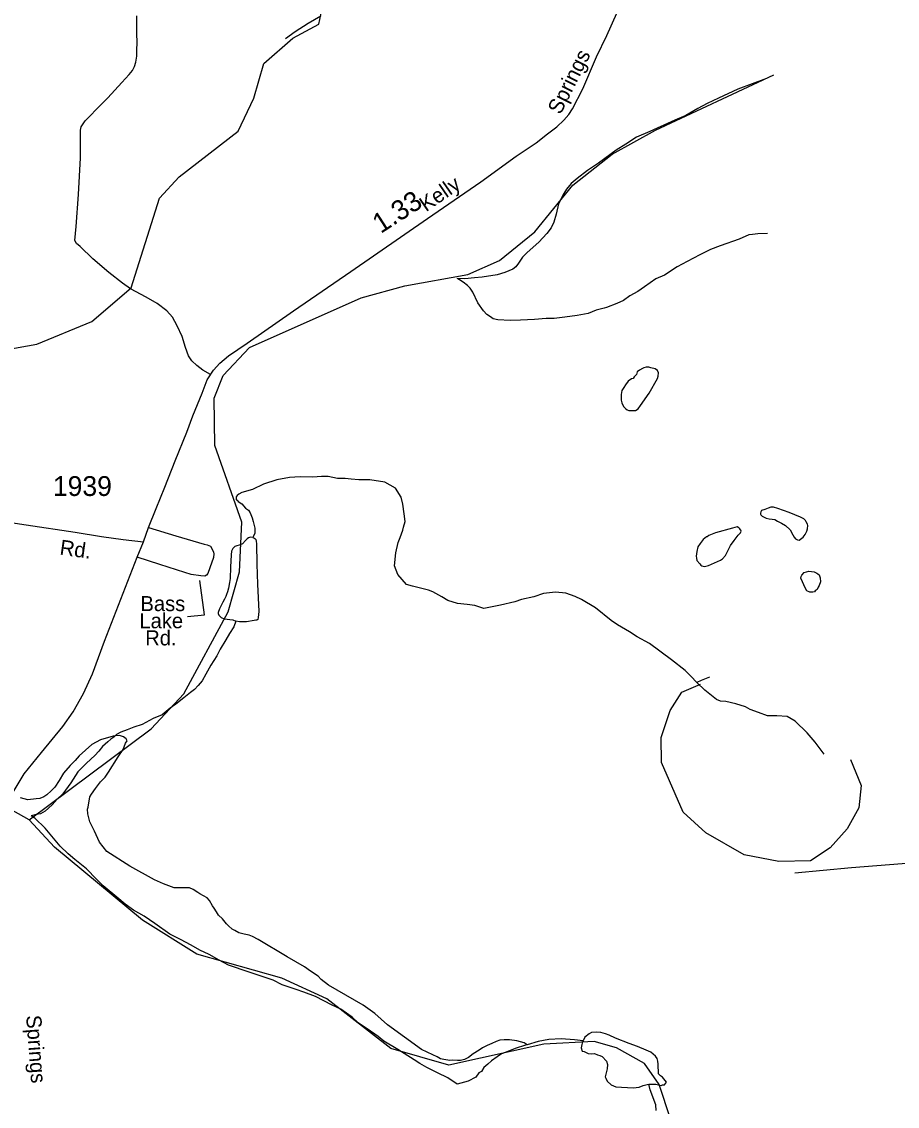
# Model space of a CAD drawing. Extents: x 2206922 to 2357709, y 510027 to 673830.
# Drawn here: x 2288307 to 2293828, y 540656 to 547499 of the extents above; entities that cross this region are included whole.
import ezdxf

# ---------------------------------------------------------------- set-up
doc = ezdxf.new("R2010")
doc.units = 0
for name, color, linetype in [('Exist Hydrographic Creek Single Shore', 7, 'Continuous'), ('Exist Hydrographic Misc Water Feature', 7, 'Continuous'), ('Exist Hydrographic Pond Under 1500 Sq Ft', 7, 'Continuous'), ('Exist Road Non-System Type 51', 7, 'Continuous'), ('Exist Road Non-System Type 51 Label', 7, 'Continuous'), ('Exist Road Secondary Mileage Hundredths English Label', 7, 'Continuous'), ('Exist Road Secondary Type 51 Attributed', 7, 'Continuous'), ('Exist Road Secondary Type 51 Label', 7, 'Continuous'), ('Exist Road Secondary Type 51 Number Label', 7, 'Continuous')]:
    doc.layers.add(name, color=color, linetype=linetype)

msp = doc.modelspace()

# ---------------------------------------------------------------- linework, layer by layer
at = {"layer": 'Exist Hydrographic Creek Single Shore'}
for points in [[(2288355, 542464.3), (2288012, 542654.8), (2287845, 542668), (2287204, 542628.5), (2286663.9, 542531.1), (2286354.9, 542537.3), (2286064, 542585.8), (2285821, 542708.8), (2285661, 542872.7), (2285557.9, 543153.6), (2285515.9, 544171.1), (2285319.8, 544601.4), (2285059, 544898.5), (2285059, 544931.3)], [(2295399.2, 540941.6), (2294538.1, 540365.3), (2293899, 540102.7), (2293469, 539773.6), (2293344.1, 539730.3), (2293186, 539720.3), (2292960.1, 539842.9), (2292683, 540107.5), (2292472, 540354.5), (2292327.1, 540793.6), (2292234, 540926.6), (2292058, 541025.3), (2291915.9, 541064.3), (2291600, 541047.7), (2291001, 540915.4), (2290634, 541021.2), (2290231, 541334.3), (2289947, 541464.7), (2289412, 541616.5), (2289069, 541830), (2288514.9, 542290.5), (2288355, 542464.3)]]:
    msp.add_lwpolyline(points, dxfattribs=at)
at = {"layer": 'Exist Hydrographic Misc Water Feature'}
for points in [[(2290015.9, 547395.9), (2290180, 547484.4), (2290267.9, 547899.1), (2290432, 548125.4), (2291134.9, 548626.1), (2291316, 548835.6), (2291685, 549497.1), (2291824.9, 549615.7), (2292390, 549784.7), (2292653.9, 550022), (2292743.9, 550207.1), (2292758.9, 550462.6), (2292714, 550765.2), (2292587.1, 551030.2), (2292292, 551400.1), (2291764, 551702.6), (2291133.9, 552299.1), (2290898.9, 552477.7), (2290807, 552486.1), (2290557.9, 552425.5), (2290143.9, 552165)], [(2290193.1, 547534.2), (2290113.9, 547487.3), (2290031.1, 547436.2), (2289970.2, 547391.8)], [(2285059, 544931.3), (2285433, 544986), (2286182.9, 544984), (2286556.9, 545045.4), (2286748, 545097.3), (2286954.9, 545240.7), (2287079, 545284.1), (2287462, 545322.3), (2287778, 545417.6), (2288202, 545428.6), (2288402, 545464), (2288749.9, 545607.9), (2288998, 545819.3), (2289176, 546386.4), (2289299.9, 546521.6), (2289672.1, 546809.3), (2289769.9, 547017.1), (2289834, 547235.6), (2290015.9, 547395.9)], [(2288355, 542464.3), (2289123.9, 543039), (2289330, 543257.9), (2289608.9, 543777), (2289681.1, 544028), (2289695, 544342.6), (2289524, 544824.8), (2289520.9, 545123.3), (2289577.9, 545266.5), (2289743, 545443.5), (2290448, 545757.3), (2290721.9, 545833.7), (2291121, 545904.4), (2291320.1, 545992.2), (2291542.9, 546174.6), (2291782, 546468.3), (2292029.9, 546663.3), (2292303.9, 546815.2), (2293050.1, 547164.2)], [(2293002.5, 547140.3), (2292821.7, 547074.7), (2292699.9, 547017.6), (2292628.7, 546982.9), (2292570.5, 546952.3), (2292495, 546907.7), (2292425.7, 546878.8), (2292268.4, 546807.6), (2292182.7, 546770.7), (2292115.5, 546726.1), (2292055.4, 546689.7), (2291944.2, 546606.7), (2291874.9, 546559.9), (2291809.5, 546509.4), (2291771.6, 546479), (2291741.8, 546442.9), (2291726.1, 546414.8), (2291691.2, 546350.4), (2291677.7, 546284.3), (2291662.1, 546234.3), (2291644.7, 546198.1), (2291618.8, 546163.8), (2291566.9, 546107.5), (2291493.7, 546042.7), (2291464.4, 546014.3), (2291438.6, 545976.4), (2291422.6, 545952.1), (2291402.9, 545938), (2291353.5, 545917.5), (2291305.3, 545903.2), (2291211.4, 545888.2), (2291161.8, 545883.9), (2291101.5, 545877.1), (2291053.7, 545878.7)], [(2293008.3, 546163), (2292947.8, 546160.3), (2292913.9, 546156.1), (2292892, 546153.7), (2292830.1, 546127.4), (2292710.7, 546086.1), (2292649.2, 546061.3), (2292583.4, 546029.1), (2292502, 545986.2), (2292440.5, 545953.7), (2292360.7, 545900.8), (2292305.1, 545876.3), (2292233.4, 545825.9), (2292191.7, 545797.3), (2292142.3, 545769.1), (2292100.5, 545740.5), (2292058.4, 545722.1), (2291994.9, 545695.6), (2291978.9, 545691.5), (2291929.3, 545679.1), (2291879, 545658.7), (2291809.5, 545646.1), (2291731.6, 545635.1), (2291663.7, 545626.6), (2291613.5, 545626.1), (2291539.7, 545621.4), (2291451.7, 545616.8), (2291386.3, 545614.1), (2291308.2, 545619.3), (2291280.1, 545624.8), (2291262.2, 545636.8), (2291239.7, 545652.8), (2291219.6, 545674.5), (2291183.1, 545726.2), (2291150.5, 545793.5), (2291134.1, 545817.5), (2291117.9, 545835.4), (2291090, 545857), (2291067.8, 545870.9), (2291053.7, 545878.7)], [(2292131.4, 545231), (2292113.2, 545209), (2292103.6, 545191), (2292091.5, 545172.9), (2292085.9, 545146.6), (2292086.3, 545110.9), (2292090.4, 545094.8), (2292100.5, 545071), (2292113, 545059), (2292124.9, 545051.1), (2292134.7, 545047.2), (2292151.1, 545045.6), (2292158.7, 545045.6), (2292177, 545045.7), (2292194.8, 545056), (2292208.8, 545077.8), (2292263.9, 545156.3), (2292315, 545248.8), (2292320.7, 545262.9), (2292322.8, 545284.9), (2292316.4, 545298.8), (2292300.2, 545308.5), (2292274, 545316.6), (2292260.2, 545320.3), (2292244.4, 545320.2), (2292230.1, 545315.9), (2292222.1, 545311.8), (2292202.2, 545301.8), (2292188.2, 545289.7), (2292182.7, 545273.5), (2292174.5, 545265.4), (2292168.8, 545259.4), (2292162.8, 545249.3), (2292152.8, 545247.2), (2292131.4, 545231)], [(2292564.7, 543330.4), (2292526.4, 543369.9), (2292490.1, 543405.7), (2292403.6, 543472.7), (2292264.7, 543575.5), (2292188, 543618.7), (2292140.3, 543650.2), (2292063.8, 543693.3), (2292023.2, 543720.9), (2291925, 543801.9), (2291836.2, 543853.3), (2291796, 543872.8), (2291738, 543894.1), (2291671.7, 543899.6), (2291598.1, 543890.8), (2291536.4, 543870.5), (2291458.5, 543853.8), (2291416.4, 543839.1), (2291325, 543818.4), (2291221.2, 543797.6), (2291164.8, 543816.9), (2291114.8, 543822.5), (2291054.9, 543827.9), (2290994.4, 543847.5), (2290956.7, 543871), (2290900.3, 543902.2), (2290872.2, 543912.1), (2290838, 543921.7), (2290771.7, 543937.4), (2290734.2, 543948.7), (2290679.3, 544012.1), (2290656.9, 544066.2), (2290666.1, 544147.9), (2290681.5, 544214.2), (2290693.2, 544246.1), (2290710.6, 544290.5), (2290714.5, 544310.6), (2290724.4, 544346.4), (2290719.5, 544394.6), (2290711.1, 544456.2), (2290700.6, 544500.4), (2290664.3, 544555.7), (2290596.2, 544593.2), (2290501.9, 544608.2), (2290432, 544609.8), (2290384, 544613), (2290345.9, 544616.7), (2290298.1, 544618.2), (2290240.3, 544629.8), (2290198, 544629.3), (2290142, 544625.1), (2290063.9, 544627.9), (2289996, 544623.6), (2289916.3, 544608.9), (2289832.2, 544582.1), (2289762.7, 544547.6), (2289695, 544529), (2289677.2, 544518.7)], [(2289677.2, 544518.7), (2289665.1, 544510.4), (2289659.5, 544502.3), (2289659.7, 544482.4), (2289665.7, 544480.7), (2289671.6, 544472.5), (2289695.8, 544456.7), (2289717.8, 544431.1), (2289738.1, 544417.5), (2289748.1, 544401.4), (2289760.6, 544369.5), (2289767, 544345.4), (2289777.4, 544303.7), (2289777.7, 544271.6), (2289769.5, 544253.8), (2289763.9, 544245.7)], [(2293238.9, 544361.9), (2293218.4, 544373.9), (2293146.3, 544403), (2293074.5, 544428.4), (2293048, 544436), (2293029.8, 544435.9), (2293014.2, 544429.7), (2292992.1, 544421.7), (2292972, 544415.4), (2292966.4, 544407.4), (2292966.2, 544399.3), (2292966.2, 544391.5), (2292966.4, 544387.5), (2292974.8, 544379.7), (2293000.5, 544367.8), (2293020.8, 544363.9), (2293038.8, 544360.4), (2293054.6, 544358.4), (2293073, 544348.7), (2293097, 544336.6), (2293123.3, 544320.9), (2293153, 544293.3), (2293169.8, 544261.5), (2293177.8, 544247.4), (2293185.8, 544237.7), (2293189.9, 544233.8), (2293197.7, 544229.8), (2293208, 544227.8), (2293218, 544234), (2293234, 544247.9), (2293247.8, 544264.1), (2293257.4, 544286.1), (2293261.3, 544300.1), (2293262.9, 544320.5), (2293261.3, 544330.1), (2293252.5, 544344.4), (2293248.8, 544352.3), (2293238.9, 544361.9)], [(2292604.5, 544232.4), (2292584.2, 544208.2), (2292570.7, 544185.9), (2292563.3, 544155.8), (2292559.4, 544127.6), (2292561.2, 544114), (2292563.7, 544099.8), (2292581.7, 544078), (2292589.7, 544069.9), (2292595.9, 544066.2), (2292611.7, 544062.1), (2292627.9, 544066.6), (2292637.9, 544068.7), (2292713.4, 544101.2), (2292725.5, 544109.5), (2292745, 544131.7), (2292776.5, 544193.9), (2292798.5, 544225.9), (2292823.7, 544260.2), (2292829.9, 544266.2), (2292839.7, 544274.4), (2292843.4, 544284.4), (2292841.5, 544290.4), (2292839.5, 544294.2), (2292835.6, 544300.6), (2292829.6, 544306.3), (2292817.6, 544312.2), (2292789.3, 544303.9), (2292681.6, 544275.1), (2292639.8, 544258.7), (2292628.3, 544250.3), (2292624, 544248.5), (2292604.5, 544232.4)], [(2289763.9, 544245.7), (2289749.8, 544247.4), (2289737.7, 544243.2), (2289728, 544237.3), (2289718, 544227.1), (2289700.1, 544205.1), (2289694.4, 544203.1), (2289678, 544197), (2289664.1, 544192.6), (2289650.7, 544188.5), (2289638.4, 544176.6), (2289630.8, 544158.3), (2289628.8, 544136.3), (2289623.5, 544058.4), (2289622.2, 543986.5), (2289616.5, 543960.5), (2289610.9, 543924.5), (2289605.2, 543902.2), (2289599.1, 543886.1), (2289593.3, 543872.4), (2289585.5, 543856.1), (2289575.9, 543838.1), (2289566, 543820.1), (2289553.9, 543796), (2289545.9, 543771.7), (2289546.8, 543765.9), (2289550.7, 543755.9), (2289552.5, 543752), (2289565, 543740), (2289584.5, 543732.2), (2289638.6, 543724.9), (2289656.7, 543716.9)], [(2289763.9, 544245.7), (2289771.7, 544243.8), (2289777.9, 544239.6), (2289784.2, 544231.7), (2289785.9, 544221.7), (2289788.3, 544206), (2289789.3, 544076.1), (2289794.7, 543950), (2289802.1, 543778.1), (2289798.4, 543740.1), (2289796.3, 543728.3), (2289790.6, 543724.3), (2289783, 543724.2), (2289772.7, 543722.1), (2289724.8, 543713.5), (2289680.9, 543713.2), (2289656.7, 543716.9)], [(2293342.5, 543965.1), (2293334.5, 543943.1), (2293328.7, 543931.1), (2293323, 543917), (2293310.5, 543909.1), (2293305, 543903), (2293295.1, 543900.9), (2293276.9, 543900.8), (2293257, 543908.6), (2293248.6, 543922.4), (2293220.5, 543988), (2293222.1, 543998.2), (2293225.8, 544008.2), (2293239.5, 544024.3), (2293269.5, 544032.4), (2293303.7, 544028.9), (2293319.7, 544020.8), (2293327.7, 544015.1), (2293335.7, 544009.1), (2293342.1, 543991.1), (2293342.5, 543965.1)], [(2289656.7, 543716.9), (2289645.2, 543680.9), (2289617.3, 543640.5), (2289593.9, 543600.2), (2289558.5, 543540.3), (2289536.9, 543497.7), (2289499.2, 543439.7), (2289468.2, 543383.2), (2289444.7, 543341.3), (2289418.8, 543310.7), (2289396.9, 543286.8), (2289371.4, 543266.3), (2289329.4, 543234.1), (2289279.8, 543193.7), (2289244.3, 543167.4), (2289192.6, 543127), (2289136.7, 543102.6), (2289067.1, 543065.6), (2289013.4, 543049.4), (2288973.2, 543032.7), (2288932, 543016.6), (2288905.8, 543002.3), (2288895.9, 542994.1)], [(2292644.1, 543363.1), (2292590.6, 543342.7), (2292564.7, 543330.4)], [(2293366.3, 542878), (2293309.7, 542953.4), (2293259.2, 543012.9), (2293184.6, 543086.2), (2293132.7, 543115.9), (2293068.5, 543119.1), (2293008.5, 543120.4), (2292952.1, 543141.9), (2292900.2, 543159.4), (2292870, 543177.4), (2292809.8, 543196.6), (2292745.8, 543210.3), (2292713.8, 543211.8), (2292687.8, 543223.5), (2292615, 543282.7), (2292564.7, 543330.4)], [(2288895.9, 542994.1), (2288884, 542992.2), (2288804.3, 542969.4), (2288748.5, 542938.8), (2288669.1, 542868.1), (2288643.3, 542837.9), (2288612.1, 542805.7), (2288570.3, 542759.3), (2288542.8, 542711.1), (2288515.1, 542670.6), (2288493.4, 542646.8), (2288465.5, 542622.6), (2288446, 542608.1), (2288421.9, 542597.9), (2288398.3, 542595.8), (2288346, 542589.1), (2288322, 542597.2), (2288299.8, 542602.9)], [(2288895.9, 542994.1), (2288887.7, 542986), (2288870.1, 542972), (2288850.4, 542955.9), (2288816.8, 542927.3), (2288793, 542897.2), (2288769.2, 542869.2), (2288715.7, 542820.5), (2288662, 542766.1), (2288617.1, 542697.9), (2288567.4, 542627.5), (2288529.9, 542595), (2288498.3, 542558.8), (2288454.7, 542518.4), (2288425.1, 542502.1), (2288398.9, 542498), (2288366.9, 542489.4)], [(2291494.8, 541043.5), (2291474.5, 541057.5), (2291428.3, 541068.9), (2291382.4, 541076.6), (2291348.4, 541076.1), (2291322.5, 541073.9), (2291298.5, 541065.8), (2291270.6, 541053.3), (2291242.8, 541039.3), (2291213.2, 541025.1), (2291191.3, 541011), (2291153.8, 540986.6), (2291124, 540964.3), (2291099.8, 540952.1), (2291074.2, 540945.9), (2291054.1, 540945.6), (2291026, 540947.4), (2291006.1, 540945.2), (2290968, 540950.9), (2290948.1, 540956.4), (2290925.7, 540968.2), (2290899.7, 540980.2), (2290827.3, 541015.5), (2290614.1, 541171.3), (2290533.7, 541242.6), (2290460.9, 541293.7), (2290242.1, 541421.5), (2290195.8, 541457.3), (2290177.3, 541477.1), (2290127.3, 541508.6), (2290091.2, 541536.3), (2289980.5, 541599.2), (2289797.3, 541709.5), (2289763.3, 541727.2), (2289741.2, 541736.6), (2289709.4, 541742.6), (2289677.2, 541750.3), (2289650.7, 541766.1), (2289635.1, 541773.7), (2289610.7, 541795.6), (2289598.6, 541807.6), (2289572.4, 541839.1), (2289548.4, 541863), (2289535.9, 541882.7), (2289521.5, 541906.8), (2289509.4, 541920.7), (2289491.4, 541954.3), (2289477.3, 541972.2), (2289429.3, 541997.7), (2289417, 542005.7), (2289388.5, 542023.3), (2289364.5, 542035), (2289338.4, 542034.9), (2289313, 542034.7), (2289268.7, 542034.1), (2289200.2, 542059.4), (2289144.5, 542084.8), (2288989.8, 542171.3), (2288844.9, 542264.1), (2288798.3, 542323.5), (2288765.7, 542393.3), (2288751.6, 542420.9), (2288737, 542451.1), (2288729, 542484.8), (2288724.5, 542500.9), (2288722.3, 542530.8), (2288725.9, 542542.8), (2288737.4, 542608.8), (2288747.3, 542625.1), (2288773.3, 542661), (2288804.7, 542703.7), (2288832.6, 542733.5), (2288854.3, 542763.9), (2288915.4, 542860.6), (2288946.8, 542908.6), (2288962.4, 542946.7), (2288972.2, 542962.7), (2288966.3, 542974.9), (2288949.9, 542986.7), (2288923.8, 542996.4), (2288895.9, 542994.1)], [(2291494.8, 541043.5), (2291484.5, 541041.4), (2291419.1, 541020.8), (2291361.3, 540998.3), (2291331.5, 540988.2), (2291305.7, 540967.8), (2291269.8, 540943.6), (2291246, 540923.2), (2291220.2, 540901.1), (2291206.5, 540876.9), (2291190.3, 540866.8), (2291170.6, 540840.9), (2291121.2, 540814.3), (2291053.5, 540795.7), (2290993.2, 540836.8), (2290928.6, 540868.4), (2290862.4, 540901.9), (2290818.3, 540927.2), (2290781.8, 540948.9), (2290679.5, 541015.8), (2290591.1, 541067.2), (2290554.8, 541096.7), (2290484.5, 541146.2), (2290428.1, 541183.5), (2290389.9, 541219.2), (2290319, 541268.4), (2290265.5, 541293.9), (2290159.1, 541348.9), (2290086.7, 541376), (2290038.1, 541393.8), (2289949.9, 541423), (2289891.9, 541452.4), (2289741.8, 541503), (2289611.2, 541547.8), (2289552.9, 541579.3), (2289488.7, 541614.5), (2289430.3, 541641.9), (2289376.2, 541673.2), (2289307.7, 541708.6), (2289241.4, 541742.2), (2289147.1, 541809.1), (2289078.4, 541856.7), (2289012, 541893.9), (2288959.9, 541931.3), (2288907.2, 541977), (2288820.9, 542048), (2288778.4, 542089.6), (2288715.9, 542155), (2288641.5, 542214.1), (2288601.1, 542249.8), (2288548.8, 542297.4), (2288455.7, 542410.3), (2288389.5, 542473.8), (2288366.9, 542489.4)], [(2291846.2, 541068.8), (2291792.1, 541076.6), (2291708, 541081.5), (2291630.1, 541078.7), (2291564.3, 541066.3), (2291494.8, 541043.5)], [(2292260.8, 540795.1), (2292276.6, 540795.2), (2292288.5, 540795.4), (2292304.3, 540795.5), (2292338.8, 540787.9), (2292346.8, 540792), (2292360.7, 540791.9), (2292372.8, 540807.9), (2292364, 540819.7), (2292356.4, 540829.8), (2292346.5, 540839.8), (2292334, 540849.4), (2292330.1, 540853.6), (2292322.1, 540861.3), (2292319.3, 540921.3), (2292317.2, 540941.5), (2292312.9, 540957.2), (2292302.9, 540973.3), (2292274.8, 540999), (2292245, 541010.8), (2292190.5, 541034), (2292136.4, 541053.5), (2292050.2, 541086.8), (2292010.3, 541104.6), (2291987.5, 541114), (2291957.8, 541121.8), (2291931.7, 541123.7), (2291899.9, 541121.2), (2291885.8, 541113.2), (2291858.3, 541093), (2291846.2, 541068.8)], [(2291846.2, 541068.8), (2291842.5, 541062.9), (2291838.2, 541046.9), (2291834.5, 541024.7), (2291841.1, 541004.8), (2291853, 541002.9), (2291879.2, 540989.3), (2291901, 540987.6), (2291918.8, 540989.8), (2291937.1, 540981.7), (2291953.1, 540976.1), (2291967, 540969.9), (2291993.4, 540940.4), (2292001.2, 540920.6), (2291997.8, 540892.3), (2291986.1, 540842.2), (2291990.8, 540834.2), (2291998.4, 540814.4), (2292023, 540792.8), (2292052.9, 540779), (2292163.2, 540772.1), (2292180.9, 540774.3), (2292200.8, 540776.2), (2292224.7, 540786.8), (2292250.8, 540795), (2292260.8, 540795.1)], [(2292308.2, 540629.5), (2292305.7, 540665.5), (2292268.8, 540761.1), (2292260.8, 540795.1)]]:
    msp.add_lwpolyline(points, dxfattribs=at)
at = {"layer": 'Exist Hydrographic Pond Under 1500 Sq Ft'}
msp.add_lwpolyline([(2293532, 542845.2), (2293600, 542679.9), (2293585.1, 542539.2), (2293511, 542406.2), (2293404, 542287), (2293279.9, 542204.2), (2293080, 542201.7), (2292863.1, 542242.1), (2292620.1, 542381.5), (2292477, 542512.3), (2292341, 542826.6), (2292339, 542984.1), (2292396, 543153.4), (2292470, 543270), (2292586, 543320.1)], dxfattribs=at)
at = {"layer": 'Exist Road Non-System Type 51'}
for points in [[(2289498.5, 545273.2), (2289449.8, 545300.5), (2289410.6, 545330.2), (2289379.8, 545359.9), (2289359.6, 545390.8), (2289340.6, 545443), (2289318.1, 545513.1), (2289288.4, 545580.8), (2289258.7, 545635.4), (2289222, 545675.7), (2289161.4, 545720.9), (2289092.6, 545762.4), (2288994.1, 545814.7), (2288941.9, 545849.1), (2288857.6, 545918), (2288755.6, 546003.5), (2288674.9, 546080.7), (2288652.3, 546100.8), (2288642.8, 546119.8), (2288649.9, 546207.7), (2288665.4, 546408.4), (2288677.2, 546639.9), (2288677.2, 546783.6), (2288678.4, 546814.5), (2288682, 546835.8), (2288690.3, 546848.9), (2288708.1, 546873.8), (2288744.9, 546911.8), (2288773.4, 546940.3), (2288850.5, 547018.7), (2288939.5, 547114.9), (2288985.8, 547167.1), (2289004.8, 547190.9), (2289017.8, 547215.8), (2289027.3, 547243.1), (2289032.1, 547282.3), (2289033.3, 547328.6), (2289034.4, 547360.7), (2289033.3, 547434.3), (2289032.4, 547536.7)], [(2289107.7, 544308.5), (2289279.8, 544256.1), (2289458.2, 544203.7), (2289477.4, 544198.4), (2289496.7, 544189.8), (2289509.5, 544167.4), (2289515.9, 544153.5), (2289518.1, 544141.7), (2289517, 544119.2), (2289493.5, 544054), (2289480.7, 544017.7), (2289473.2, 544007), (2289461.4, 544000.6), (2289436.8, 544002.7), (2289376.4, 544012), (2289336.2, 544023.6), (2289177.9, 544074.2), (2289035.5, 544120.8)], [(2293182.1, 542128.7), (2293539.5, 542164.1), (2294017.8, 542201.3), (2294272, 542223)]]:
    msp.add_lwpolyline(points, dxfattribs=at)
at = {"layer": 'Exist Road Non-System Type 51 Label'}
msp.add_lwpolyline([(2289352, 543745.7), (2289460.1, 543757.8), (2289430.1, 543974.1)], dxfattribs=at)
at = {"layer": 'Exist Road Secondary Type 51 Attributed'}
for points in [[(2289075, 544218.8), (2289107.7, 544308.5), (2289154.7, 544428.2), (2289209.2, 544563), (2289275.5, 544729.8), (2289348.1, 544910.4), (2289385.5, 545013.1), (2289445.4, 545156.4), (2289476.4, 545239.8), (2289517, 545300.7), (2289555.5, 545345.6), (2289612.1, 545391.6), (2289729.1, 545471.8), (2290020.8, 545675.5), (2290381.5, 545922.4), (2290865.6, 546257.6), (2291202.2, 546488.6), (2291424.3, 546651.7), (2291551.1, 546735.6), (2291621.6, 546791.2), (2291681.4, 546837.1), (2291724.2, 546877.8), (2291756.2, 546913), (2291779.4, 546949), (2291846, 547075.6), (2291931.4, 547277.9), (2291995.8, 547412), (2292060.3, 547553.1)], [(2286580.7, 544537.9), (2286630.1, 544533.6), (2286800.8, 544515.5), (2286965.1, 544496.7), (2287059.7, 544487), (2287351.4, 544459.8), (2287648, 544429.3), (2287946.1, 544384.4), (2288335.6, 544325.1), (2288643.4, 544278.6), (2288810.1, 544251.3), (2288947.9, 544232), (2289075, 544218.8)], [(2288230, 540524.1), (2288185.2, 540913.8), (2288140.5, 541294), (2288100.2, 541630.7), (2288091.2, 541861.2), (2288099.5, 542029.1), (2288114, 542203.2), (2288148.4, 542363.4), (2288202.8, 542539.9), (2288247.9, 542628.3), (2288322.7, 542754.7), (2288431.3, 542889.7), (2288565.8, 543052.9), (2288630.8, 543145.6), (2288697.7, 543260), (2288754.6, 543384.6), (2288828.5, 543591.2), (2289035.5, 544120.8), (2289075, 544218.8)]]:
    msp.add_lwpolyline(points, dxfattribs=at)

# ---------------------------------------------------------------- texts
at = {"layer": 'Exist Road Non-System Type 51 Label'}
for s, p in [('Bass', (2289055.8, 543780.7)), ('Lake', (2289049.3, 543672.5)), ('Rd.', (2289085.9, 543564.4))]:
    msp.add_text(s, height=95, dxfattribs=at).set_placement(p)
at = {"layer": 'Exist Road Secondary Mileage Hundredths English Label'}
msp.add_text('1.33', height=125, rotation=32.93333, dxfattribs=at).set_placement((2290570.9, 546159.8))
at = {"layer": 'Exist Road Secondary Type 51 Label'}
for s, rotation, p in [('Springs', 63.4615, (2291703.7, 546908.1)), ('Kelly', 34.64337, (2290856.4, 546296.6)), ('Rd.', 351.89026, (2288543.1, 544138.2)), ('Springs', 274.3252, (2288334.9, 541228.5))]:
    msp.add_text(s, height=95, rotation=rotation, dxfattribs=at).set_placement(p)
at = {"layer": 'Exist Road Secondary Type 51 Number Label'}
msp.add_text('1939', height=125, dxfattribs=at).set_placement((2288504, 544507.2))

doc.saveas('drawing.dxf')
